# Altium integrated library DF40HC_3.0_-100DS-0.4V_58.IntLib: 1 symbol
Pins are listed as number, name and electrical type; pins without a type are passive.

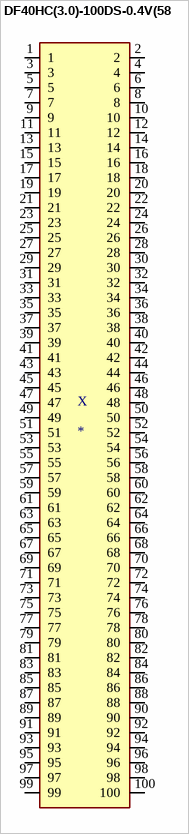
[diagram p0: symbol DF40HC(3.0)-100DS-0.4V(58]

## DF40HC(3.0)-100DS-0.4V(58
designator X
100 Position Connector Receptacle, Center Strip Contacts Surface Mount Gold; MP: DF40HC_3.0_-100DS-0.4V_58; MF: Hirose Electric
footprint HRS_DF40HC(3.0)-100DS-0.4V(58
pins: 1, 2, 3, 4, 5, 6, 7, 8, 9, 10, 11, 12, 13, 14, 15, 16, 17, 18, 19, 20, 21, 22, 23, 24, 25, 26, 27, 28, 29, 30, 31, 32, 33, 34, 35, 36, 37, 38, 39, 40, 41, 42, 43, 44, 45, 46, 47, 48, 49, 50, 51, 52, 53, 54, 55, 56, 57, 58, 59, 60, 61, 62, 63, 64, 65, 66, 67, 68, 69, 70, 71, 72, 73, 74, 75, 76, 77, 78, 79, 80, 81, 82, 83, 84, 85, 86, 87, 88, 89, 90, 91, 92, 93, 94, 95, 96, 97, 98, 99, 100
